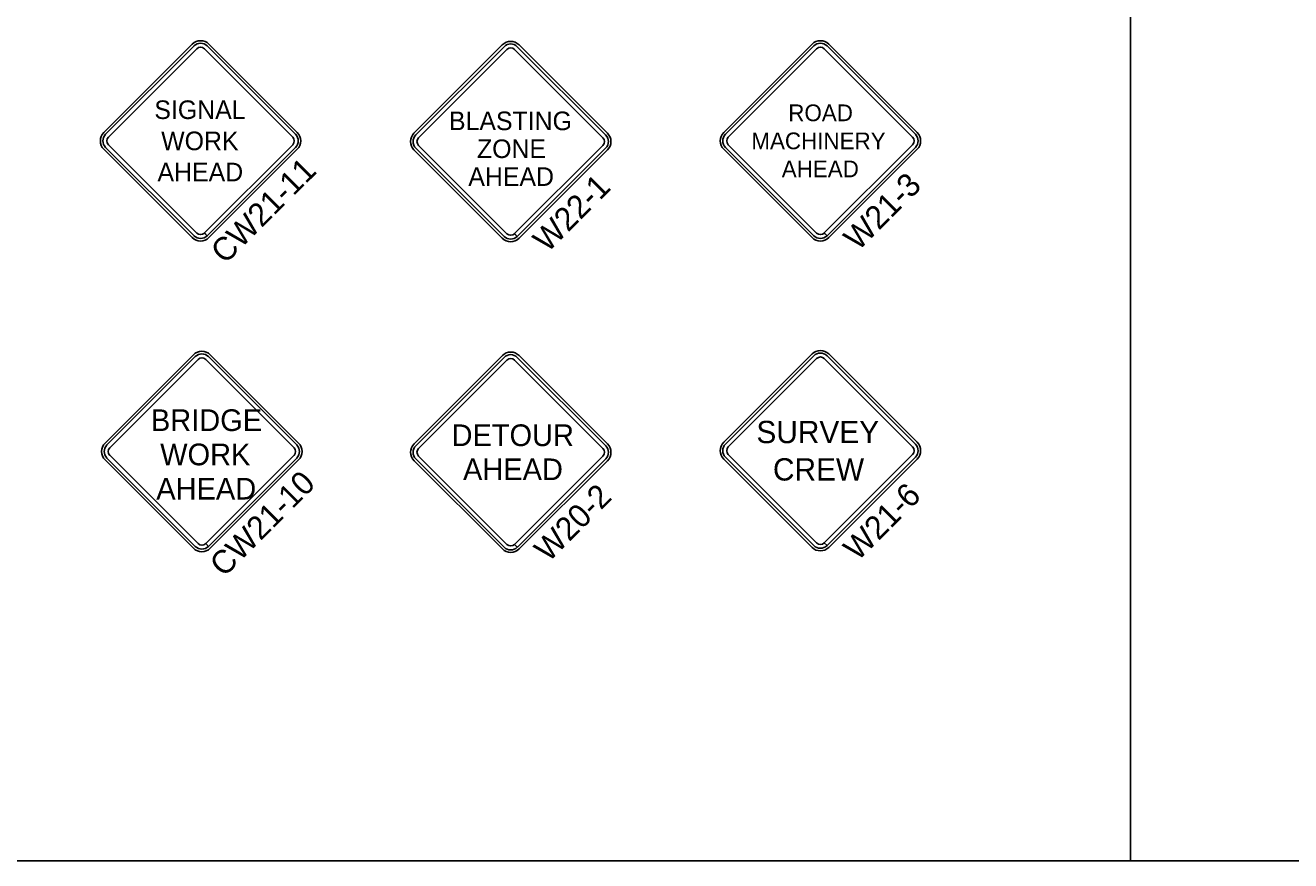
# Model space of a CAD drawing. Extents: x 1458 to 4498, y 17709 to 24109.
# Drawn here: x 2865 to 3682, y 22109 to 22648 of the extents above; entities that cross this region are included whole.
import ezdxf

# ---------------------------------------------------------------- set-up
doc = ezdxf.new("R2010")
doc.units = 0
doc.layers.add('P_ODOT_PLAN_TBlock', color=7, linetype='Continuous')
doc.layers.add('P_TRAF_TCP_General', color=7, linetype='Continuous')

msp = doc.modelspace()

# ---------------------------------------------------------------- linework, layer by layer
at = {"layer": 'P_ODOT_PLAN_TBlock'}
msp.add_line((3578.44, 23153.55), (3578.44, 22109.14), dxfattribs=at)
at = {"layer": 'P_TRAF_TCP_General'}
for p, q in [((2973.01, 22636.24), (2916.01, 22579.24)), ((2974.2, 22635.06), (2917.19, 22578.05)), ((2974.2, 22635.06), (2917.19, 22578.05)), ((2974.2, 22635.06), (2917.19, 22578.05)), ((3039.68, 22578.05), (2982.68, 22635.06)), ((3039.68, 22578.05), (2982.68, 22635.06)), ((3039.68, 22578.05), (2982.68, 22635.06)), ((3040.87, 22579.24), (2983.86, 22636.24)), ((3173.15, 22635.8), (3116.14, 22578.79)), ((3241.01, 22578.79), (3184, 22635.8)), ((3373.01, 22636.24), (3316.01, 22579.24)), ((3374.2, 22635.06), (3317.19, 22578.05)), ((3374.2, 22635.06), (3317.19, 22578.05)), ((3374.2, 22635.06), (3317.19, 22578.05)), ((3439.68, 22578.05), (3382.68, 22635.06)), ((3439.68, 22578.05), (3382.68, 22635.06)), ((3439.68, 22578.05), (3382.68, 22635.06)), ((3440.87, 22579.24), (3383.86, 22636.24)), ((2918.96, 22576.29), (2975.96, 22633.29)), ((2918.96, 22576.29), (2975.96, 22633.29)), ((2980.91, 22633.29), (3037.92, 22576.29)), ((2980.91, 22633.29), (3037.92, 22576.29)), ((3174.33, 22634.62), (3117.33, 22577.61)), ((3119.1, 22575.84), (3176.1, 22632.85)), ((3181.05, 22632.85), (3238.05, 22575.84)), ((3239.82, 22577.61), (3182.82, 22634.62)), ((3318.96, 22576.29), (3375.96, 22633.29)), ((3318.96, 22576.29), (3375.96, 22633.29)), ((3380.91, 22633.29), (3437.92, 22576.29)), ((3380.91, 22633.29), (3437.92, 22576.29)), ((2917.19, 22569.57), (2974.2, 22512.57)), ((2917.19, 22569.57), (2974.2, 22512.57)), ((2917.19, 22569.57), (2974.2, 22512.57)), ((2975.96, 22514.33), (2918.96, 22571.34)), ((2975.96, 22514.33), (2918.96, 22571.34)), ((3037.92, 22571.34), (2980.93, 22514.35)), ((3037.92, 22571.34), (2980.93, 22514.35)), ((2982.68, 22512.57), (3039.68, 22569.57)), ((2982.7, 22512.58), (3039.68, 22569.57)), ((2982.7, 22512.58), (3039.68, 22569.57)), ((3176.1, 22513.89), (3119.1, 22570.9)), ((3238.05, 22570.9), (3181.07, 22513.91)), ((3317.19, 22569.57), (3374.2, 22512.57)), ((3317.19, 22569.57), (3374.2, 22512.57)), ((3317.19, 22569.57), (3374.2, 22512.57)), ((3375.96, 22514.33), (3318.96, 22571.34)), ((3375.96, 22514.33), (3318.96, 22571.34)), ((3437.92, 22571.34), (3380.93, 22514.35)), ((3437.92, 22571.34), (3380.93, 22514.35)), ((3382.68, 22512.57), (3439.68, 22569.57)), ((3382.7, 22512.58), (3439.68, 22569.57)), ((3382.7, 22512.58), (3439.68, 22569.57)), ((2916.01, 22568.39), (2973.01, 22511.38)), ((2983.86, 22511.38), (3040.87, 22568.39)), ((3116.14, 22567.94), (3173.15, 22510.94)), ((3117.33, 22569.13), (3174.33, 22512.12)), ((3182.83, 22512.14), (3239.82, 22569.13)), ((3184, 22510.94), (3241.01, 22567.94)), ((3316.01, 22568.39), (3373.01, 22511.38)), ((3383.86, 22511.38), (3440.87, 22568.39)), ((2982.68, 22512.57), (2980.91, 22514.33)), ((2982.68, 22512.57), (2980.91, 22514.33)), ((2980.93, 22514.35), (2982.7, 22512.58)), ((2980.93, 22514.35), (2982.7, 22512.58)), ((3182.82, 22512.12), (3181.05, 22513.89)), ((3182.82, 22512.12), (3181.05, 22513.89)), ((3181.07, 22513.91), (3182.83, 22512.14)), ((3181.07, 22513.91), (3182.83, 22512.14)), ((3382.68, 22512.57), (3380.91, 22514.33)), ((3382.68, 22512.57), (3380.91, 22514.33)), ((3380.93, 22514.35), (3382.7, 22512.58)), ((3380.93, 22514.35), (3382.7, 22512.58)), ((2973.84, 22435.72), (2916.83, 22378.71)), ((2975.02, 22434.54), (2918.02, 22377.53)), ((2975.02, 22434.54), (2918.02, 22377.53)), ((2975.02, 22434.54), (2918.02, 22377.53)), ((2919.79, 22375.76), (2976.79, 22432.77)), ((2919.79, 22375.76), (2976.79, 22432.77)), ((2981.74, 22432.77), (3038.74, 22375.76)), ((2981.74, 22432.77), (3038.74, 22375.76)), ((3040.51, 22377.53), (2983.51, 22434.54)), ((3040.51, 22377.53), (2983.51, 22434.54)), ((3040.51, 22377.53), (2983.51, 22434.54)), ((3041.69, 22378.71), (2984.69, 22435.72)), ((3173.17, 22435.22), (3116.17, 22378.22)), ((3174.36, 22434.04), (3117.35, 22377.03)), ((3174.36, 22434.04), (3117.35, 22377.03)), ((3119.12, 22375.27), (3176.13, 22432.27)), ((3119.12, 22375.27), (3176.13, 22432.27)), ((3181.07, 22432.27), (3238.08, 22375.27)), ((3181.07, 22432.27), (3238.08, 22375.27)), ((3239.85, 22377.03), (3182.84, 22434.04)), ((3239.85, 22377.03), (3182.84, 22434.04)), ((3241.03, 22378.22), (3184.02, 22435.22)), ((3373.01, 22436.24), (3316.01, 22379.24)), ((3374.2, 22435.06), (3317.19, 22378.05)), ((3374.2, 22435.06), (3317.19, 22378.05)), ((3374.2, 22435.06), (3317.19, 22378.05)), ((3318.96, 22376.29), (3375.96, 22433.29)), ((3318.96, 22376.29), (3375.96, 22433.29)), ((3380.91, 22433.29), (3437.92, 22376.29)), ((3380.91, 22433.29), (3437.92, 22376.29)), ((3439.68, 22378.05), (3382.68, 22435.06)), ((3439.68, 22378.05), (3382.68, 22435.06)), ((3439.68, 22378.05), (3382.68, 22435.06)), ((3440.87, 22379.24), (3383.86, 22436.24)), ((2916.83, 22367.86), (2973.84, 22310.86)), ((2918.02, 22369.05), (2975.02, 22312.04)), ((2918.02, 22369.05), (2975.02, 22312.04)), ((2918.02, 22369.05), (2975.02, 22312.04)), ((2976.79, 22313.81), (2919.79, 22370.82)), ((2976.79, 22313.81), (2919.79, 22370.82)), ((3038.74, 22370.82), (2981.76, 22313.83)), ((3038.74, 22370.82), (2981.76, 22313.83)), ((2983.51, 22312.04), (3040.51, 22369.05)), ((2983.52, 22312.06), (3040.51, 22369.05)), ((2983.52, 22312.06), (3040.51, 22369.05)), ((2984.69, 22310.86), (3041.69, 22367.86)), ((3116.17, 22367.37), (3173.17, 22310.36)), ((3117.35, 22368.55), (3174.36, 22311.55)), ((3117.35, 22368.55), (3174.36, 22311.55)), ((3176.13, 22313.31), (3119.12, 22370.32)), ((3238.08, 22370.32), (3181.09, 22313.33)), ((3238.08, 22370.32), (3181.09, 22313.33)), ((3182.86, 22311.57), (3239.85, 22368.55)), ((3182.86, 22311.57), (3239.85, 22368.55)), ((3184.02, 22310.36), (3241.03, 22367.37)), ((3316.01, 22368.39), (3373.01, 22311.38)), ((3317.19, 22369.57), (3374.2, 22312.57)), ((3317.19, 22369.57), (3374.2, 22312.57)), ((3317.19, 22369.57), (3374.2, 22312.57)), ((3375.96, 22314.33), (3318.96, 22371.34)), ((3375.96, 22314.33), (3318.96, 22371.34)), ((3437.92, 22371.34), (3380.93, 22314.35)), ((3437.92, 22371.34), (3380.93, 22314.35)), ((3382.68, 22312.57), (3439.68, 22369.57)), ((3382.7, 22312.58), (3439.68, 22369.57)), ((3382.7, 22312.58), (3439.68, 22369.57)), ((3383.86, 22311.38), (3440.87, 22368.39)), ((2983.51, 22312.04), (2981.74, 22313.81)), ((2983.51, 22312.04), (2981.74, 22313.81)), ((2981.76, 22313.83), (2983.52, 22312.06)), ((2981.76, 22313.83), (2983.52, 22312.06)), ((3182.84, 22311.55), (3181.07, 22313.31)), ((3182.84, 22311.55), (3181.07, 22313.31)), ((3181.09, 22313.33), (3182.86, 22311.57)), ((3181.09, 22313.33), (3182.86, 22311.57)), ((3382.68, 22312.57), (3380.91, 22314.33)), ((3382.68, 22312.57), (3380.91, 22314.33)), ((3380.93, 22314.35), (3382.7, 22312.58)), ((3380.93, 22314.35), (3382.7, 22312.58))]:
    msp.add_line(p, q, dxfattribs=at)
msp.add_lwpolyline([(4498.44, 24109.14), (1458.44, 24109.14), (1458.44, 22109.14), (4498.44, 22109.14)], close=True, dxfattribs=at)
for centre, radius, start, end in [((2978.44, 22630.82), 7.67, 45, 135), ((2978.44, 22630.82), 6, 45, 135), ((2978.44, 22630.82), 6, 45, 135), ((2978.44, 22630.82), 6, 45, 135), ((3178.57, 22630.37), 7.67, 45, 135), ((3178.57, 22630.37), 6, 45, 135), ((3378.44, 22630.82), 7.67, 45, 135), ((3378.44, 22630.82), 6, 45, 135), ((3378.44, 22630.82), 6, 45, 135), ((3378.44, 22630.82), 6, 45, 135), ((2978.44, 22630.82), 3.5, 45, 135), ((2978.44, 22630.82), 3.5, 45, 135), ((3178.57, 22630.37), 3.5, 45, 135), ((3378.44, 22630.82), 3.5, 45, 135), ((3378.44, 22630.82), 3.5, 45, 135), ((2921.43, 22573.81), 7.67, 135, 225), ((2921.43, 22573.81), 6, 135, 225), ((2921.43, 22573.81), 6, 135, 225), ((2921.43, 22573.81), 6, 135, 225), ((3035.44, 22573.81), 6, 315, 45), ((3035.44, 22573.81), 6, 315, 45), ((3035.44, 22573.81), 6, 315, 45), ((3035.44, 22573.81), 7.67, 315, 45), ((3121.57, 22573.37), 7.67, 135, 225), ((3121.57, 22573.37), 6, 135, 225), ((3235.58, 22573.37), 6, 315, 45), ((3235.58, 22573.37), 7.67, 315, 45), ((3321.43, 22573.81), 7.67, 135, 225), ((3321.43, 22573.81), 6, 135, 225), ((3321.43, 22573.81), 6, 135, 225), ((3321.43, 22573.81), 6, 135, 225), ((3435.44, 22573.81), 6, 315, 45), ((3435.44, 22573.81), 6, 315, 45), ((3435.44, 22573.81), 6, 315, 45), ((3435.44, 22573.81), 7.67, 315, 45), ((2921.43, 22573.81), 3.5, 135, 225), ((2921.43, 22573.81), 3.5, 135, 225), ((3035.44, 22573.81), 3.5, 315, 45), ((3035.44, 22573.81), 3.5, 315, 45), ((3121.57, 22573.37), 3.5, 135, 225), ((3235.58, 22573.37), 3.5, 315, 45), ((3321.43, 22573.81), 3.5, 135, 225), ((3321.43, 22573.81), 3.5, 135, 225), ((3435.44, 22573.81), 3.5, 315, 45), ((3435.44, 22573.81), 3.5, 315, 45), ((2978.44, 22516.81), 6, 225, 315), ((2978.44, 22516.81), 6, 225, 315), ((2978.44, 22516.81), 6, 225, 315), ((2978.44, 22516.81), 3.5, 225, 315), ((2978.44, 22516.81), 3.5, 225, 315), ((3178.57, 22516.36), 3.5, 225, 315), ((3378.44, 22516.81), 6, 225, 315), ((3378.44, 22516.81), 6, 225, 315), ((3378.44, 22516.81), 6, 225, 315), ((3378.44, 22516.81), 3.5, 225, 315), ((3378.44, 22516.81), 3.5, 225, 315), ((2978.44, 22516.81), 7.67, 225, 315), ((3178.57, 22516.36), 7.67, 225, 315), ((3178.57, 22516.36), 6, 225, 315), ((3378.44, 22516.81), 7.67, 225, 315), ((2979.26, 22430.3), 7.67, 45, 135), ((2979.26, 22430.3), 6, 45, 135), ((2979.26, 22430.3), 6, 45, 135), ((2979.26, 22430.3), 6, 45, 135), ((2979.26, 22430.3), 3.5, 45, 135), ((2979.26, 22430.3), 3.5, 45, 135), ((3178.6, 22429.8), 7.67, 45, 135), ((3178.6, 22429.8), 6, 45, 135), ((3178.6, 22429.8), 6, 45, 135), ((3178.6, 22429.8), 3.5, 45, 135), ((3178.6, 22429.8), 3.5, 45, 135), ((3378.44, 22430.82), 7.67, 45, 135), ((3378.44, 22430.82), 6, 45, 135), ((3378.44, 22430.82), 6, 45, 135), ((3378.44, 22430.82), 6, 45, 135), ((3378.44, 22430.82), 3.5, 45, 135), ((3378.44, 22430.82), 3.5, 45, 135), ((2922.26, 22373.29), 7.67, 135, 225), ((2922.26, 22373.29), 6, 135, 225), ((2922.26, 22373.29), 6, 135, 225), ((2922.26, 22373.29), 6, 135, 225), ((2922.26, 22373.29), 3.5, 135, 225), ((2922.26, 22373.29), 3.5, 135, 225), ((3036.27, 22373.29), 3.5, 315, 45), ((3036.27, 22373.29), 3.5, 315, 45), ((3036.27, 22373.29), 6, 315, 45), ((3036.27, 22373.29), 6, 315, 45), ((3036.27, 22373.29), 6, 315, 45), ((3036.27, 22373.29), 7.67, 315, 45), ((3121.59, 22372.79), 7.67, 135, 225), ((3121.59, 22372.79), 6, 135, 225), ((3121.59, 22372.79), 6, 135, 225), ((3121.59, 22372.79), 3.5, 135, 225), ((3121.59, 22372.79), 3.5, 135, 225), ((3235.61, 22372.79), 3.5, 315, 45), ((3235.61, 22372.79), 3.5, 315, 45), ((3235.61, 22372.79), 6, 315, 45), ((3235.61, 22372.79), 6, 315, 45), ((3235.61, 22372.79), 7.67, 315, 45), ((3321.43, 22373.81), 7.67, 135, 225), ((3321.43, 22373.81), 6, 135, 225), ((3321.43, 22373.81), 6, 135, 225), ((3321.43, 22373.81), 6, 135, 225), ((3321.43, 22373.81), 3.5, 135, 225), ((3321.43, 22373.81), 3.5, 135, 225), ((3435.44, 22373.81), 3.5, 315, 45), ((3435.44, 22373.81), 3.5, 315, 45), ((3435.44, 22373.81), 6, 315, 45), ((3435.44, 22373.81), 6, 315, 45), ((3435.44, 22373.81), 6, 315, 45), ((3435.44, 22373.81), 7.67, 315, 45), ((2979.26, 22316.28), 7.67, 225, 315), ((2979.26, 22316.28), 6, 225, 315), ((2979.26, 22316.28), 6, 225, 315), ((2979.26, 22316.28), 6, 225, 315), ((2979.26, 22316.28), 3.5, 225, 315), ((2979.26, 22316.28), 3.5, 225, 315), ((3178.6, 22315.79), 7.67, 225, 315), ((3178.6, 22315.79), 6, 225, 315), ((3178.6, 22315.79), 6, 225, 315), ((3178.6, 22315.79), 3.5, 225, 315), ((3178.6, 22315.79), 3.5, 225, 315), ((3378.44, 22316.81), 7.67, 225, 315), ((3378.44, 22316.81), 6, 225, 315), ((3378.44, 22316.81), 6, 225, 315), ((3378.44, 22316.81), 6, 225, 315), ((3378.44, 22316.81), 3.5, 225, 315), ((3378.44, 22316.81), 3.5, 225, 315)]:
    msp.add_arc(centre, radius, start, end, dxfattribs=at)

# ---------------------------------------------------------------- texts
for s, height, p in [('SIGNAL', 12, (2948.62, 22587.93)), ('ROAD', 10.8, (3357.67, 22586.52)), ('BLASTING', 11.995, (3138.73, 22580.73)), ('WORK', 12, (2953.01, 22567.81)), ('MACHINERY', 10.8, (3333.85, 22568.41)), ('ZONE', 11.995, (3156.82, 22562.74)), ('AHEAD', 12, (2950.63, 22547.7)), ('AHEAD', 11.995, (3151.22, 22544.75)), ('AHEAD', 10.8, (3353.48, 22550.31)), ('BRIDGE', 13.994, (2946.4, 22386.51)), ('DETOUR', 13.994, (3140.39, 22376.79)), ('SURVEY', 14.4, (3337.12, 22378.68)), ('WORK', 13.994, (2952.38, 22364.4)), ('AHEAD', 13.994, (3147.8, 22354.8)), ('CREW', 14.4, (3347.8, 22354.54)), ('AHEAD', 13.994, (2949.86, 22342.29))]:
    msp.add_text(s, height=height, dxfattribs=at).set_placement(p)
for s, p in [('CW21-11', (2994.23, 22493.73)), ('W22-1', (3202.22, 22501.13)), ('W21-3', (3402.74, 22502.24)), ('CW21-10', (2993.52, 22291.66)), ('W20-2', (3202.94, 22301.26)), ('W21-6', (3402.46, 22301.96))]:
    msp.add_text(s, height=14.994, rotation=45, dxfattribs=at).set_placement(p)

doc.saveas('drawing.dxf')
